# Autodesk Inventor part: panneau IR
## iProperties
Created: 2010-07
Part Number: panneau IR
Document SubType Name: Modeling
Designer: eric
Density: 1 g/cm^3
Mass: 0.243763 g
Surface Area: 5.4898 cm^2
Volume: 0.243763 cm^3
Author: eric
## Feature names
1. Extrusion1
2. Fillet4
3. Fillet3
4. Fillet2
5. Fillet1
